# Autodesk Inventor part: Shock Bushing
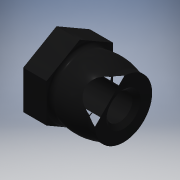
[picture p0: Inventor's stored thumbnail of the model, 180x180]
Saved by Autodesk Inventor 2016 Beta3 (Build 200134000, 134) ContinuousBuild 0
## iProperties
Shininess: 50.0
Compacted: True
Length Units: 11272
Angle Units: 11279
Time Units: 11290
Mass Units: 11286
Length Display Precision: 4
Angle Display Precision: 2
Company: Autodesk
Created: 2000-07
Part Number: Shock Bushing
Project: Inventor Samples
Document SubType Name: Modeling
Designer: Autodesk, Inc.
Density: 1.13 g/cm^3
Mass: 0.177954 g
Surface Area: 2.27867 cm^2
Volume: 0.157481 cm^3
Material: Nylon-6/6
Appearance: Glossy - Black
Density: 0.0
Volumn: 0.0
Area: 0.0
PropertySet Name: Model Information
Control State: 0
Master: False
Checked Out: False
Author: Autodesk, Inc.
Revision Number: A
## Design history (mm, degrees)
node "Revolution1" dims "d9" = 90 deg
  sketch "Sketch3"
    geometry: L1 (-7.537, 0.965)-(-13.29, 0.965); L2 (-13.29, 0.965)-(-13.29, 2.895); L3 (-13.29, 2.895)-(-11.068, 2.895); L4 (-11.068, 2.895)-(-11.068, 2.452); L5 (-7.537, 0.965)-(-7.537, 2.452); L6 (-13.29, -0.28)-(-7.606, -0.28); A1 r 5.08 centre (-9.303, -2.312) between (-7.537, 2.452) and (-11.068, 2.452)
    constraints: 12 end point, 3 parallel, 2 perpendicular, 2 point on circle, 1 centre point, 1 horizontal, 1 horizontal alignment, 1 point on line, 1 other
    dimensions: "d1" = 2.4892 diameter of L1 L6; "d2" = 6.35 diameter of L3 L6; "d3" = 2.2225 distance of L2.end L3.end; "d4" = 6.096 dimension on A1 L6; "d7" = 3.9878 distance from line of A1.centre L2; "d10" = 5.08 radius of A1
node "Extrusion1" dims "d14" = 25.4, "d15" = 0
  sketch "Sketch4"
    geometry: L1 (-3.175, -1.833)-(-3.175, 1.833); L2 (-3.175, 1.833)-(0, 3.666); L3 (0, 3.666)-(3.175, 1.833); L4 (3.175, 1.833)-(3.175, -1.833); L5 (3.175, -1.833)-(0, -3.666); L6 (0, -3.666)-(-3.175, -1.833); C1 r 3.175 at (0, 0) reference
    constraints: 12 end point, 6 tangent, 3 parallel, 2 equal length, 1 vertical
node "Extrusion2" dims "d17" = 0.635, "d18" = 0
  sketch "Sketch5"
    geometry: C1 r 1.245 at (0, 0) reference; C2 r 2.731 at (0, 0) reference
node "Fillet1" dims "d16" = 0.381
node "Chamfer1" dims "d12" = 0.381, "d13" = 0.381, "d19" = 45 deg
body "Solid1"
other parameters: "d11" = 6.0706 (derived), "d20" = 0
